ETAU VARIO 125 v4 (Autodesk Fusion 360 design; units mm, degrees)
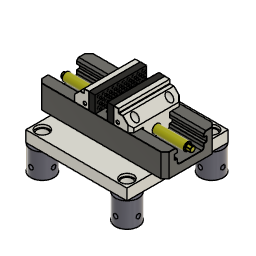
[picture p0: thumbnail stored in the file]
base_feature "Base Feature1" OffsetX 0 OffsetY 0 OffsetZ 0 OffsetX 0 OffsetY 0 OffsetZ 0 OffsetX 0 OffsetY 0 OffsetZ 0 OffsetX 0 OffsetY 0 OffsetZ 0
base_feature "Base Feature1" OffsetX 0 OffsetY 0 OffsetZ 0 OffsetX 0 OffsetY 0 OffsetZ 0 OffsetX 0 OffsetY 0 OffsetZ 0 OffsetX 0 OffsetY 0 OffsetZ 0
work_plane "WorkPlane2" User Parameter 30 named "Ouverture"
base_feature "Base Feature1"
position "Position1"
sketch "Sketch1" plane through (9.1729, 31.8972, 315) normal (1, 0, 0) x axis (0, 1, 0)
work_axis "WorkAxis1"
work_point "WorkPoint1"
joint_origin "JointOrigin7" OffsetX 0 OffsetY 0 OffsetZ 0
work_point "WorkPoint2"
work_point "WorkPoint1"
position "Position2"
position "Position3"
joint_origin "JointOrigin8" OffsetX 0 OffsetY 0 OffsetZ 0
joint_origin "JointOrigin3" OffsetX 0 OffsetY 0 OffsetZ 0
position "Position4"
ground "Terre5"
position "Position5"
ground "Terre6"
joint "Assembler5" alignOffsetX 0 alignOffsetY 0 alignOffsetZ 0
joint "Assembler6" alignOffsetX 0 alignOffsetY 0 alignOffsetZ 0
position "Position6" TranslateAlongZ -15 (= "-Ouverture / 2") TranslateAlongZ 15 (= "Ouverture / 2")
as_built_joint "Réelle"
base_feature "Fonction de base"
position "Position7"
rectangular_pattern "00000000-0000-0000-0000-000000000000" uSpaceDistance -206 vSpaceDistance 206
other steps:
create_component "CreateComponent1"
create_component "CreateComponent1"
create_component "CreateComponent2"
create_component "CreateComponent2"
create_component "CreateComponent3"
